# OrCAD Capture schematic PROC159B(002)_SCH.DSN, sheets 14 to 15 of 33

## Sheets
14 12. ETHERNET POWERS: size C; title: ETHERNET POWERS
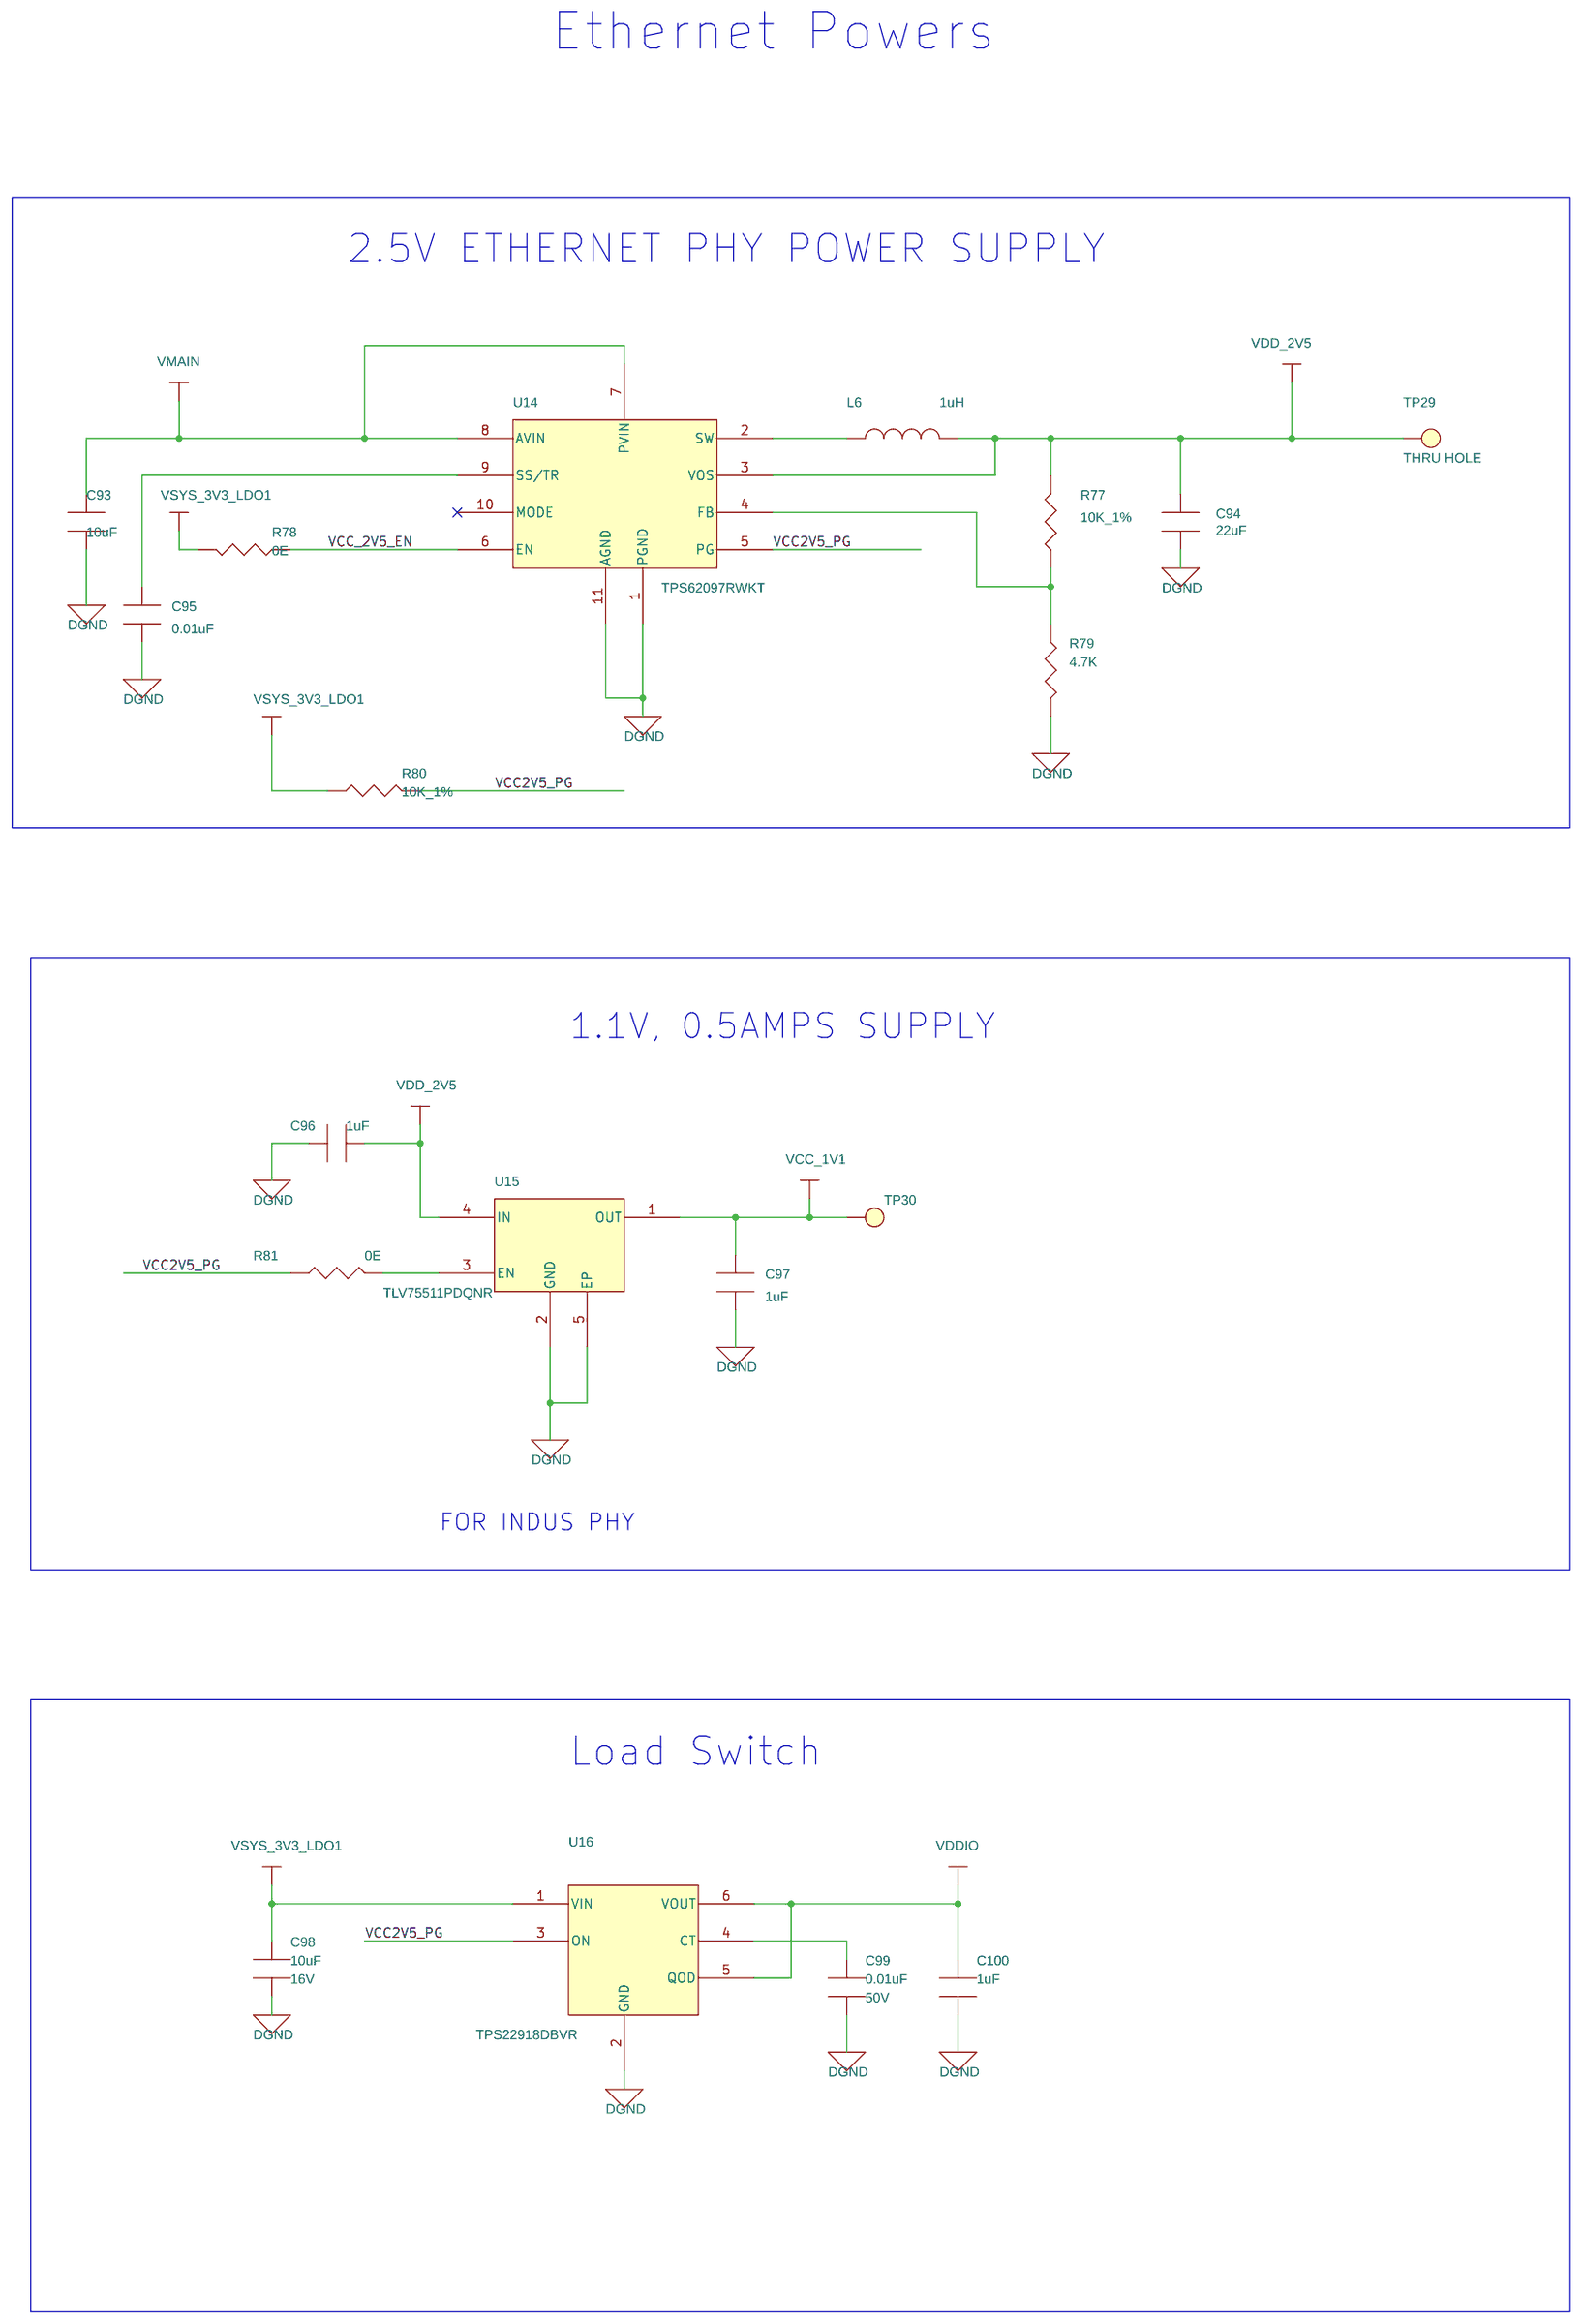
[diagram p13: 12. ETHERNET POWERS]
15 19. SOC-ICSS DP8386(Indust): size C; title: SOC-ICSS DP8386(Indus)
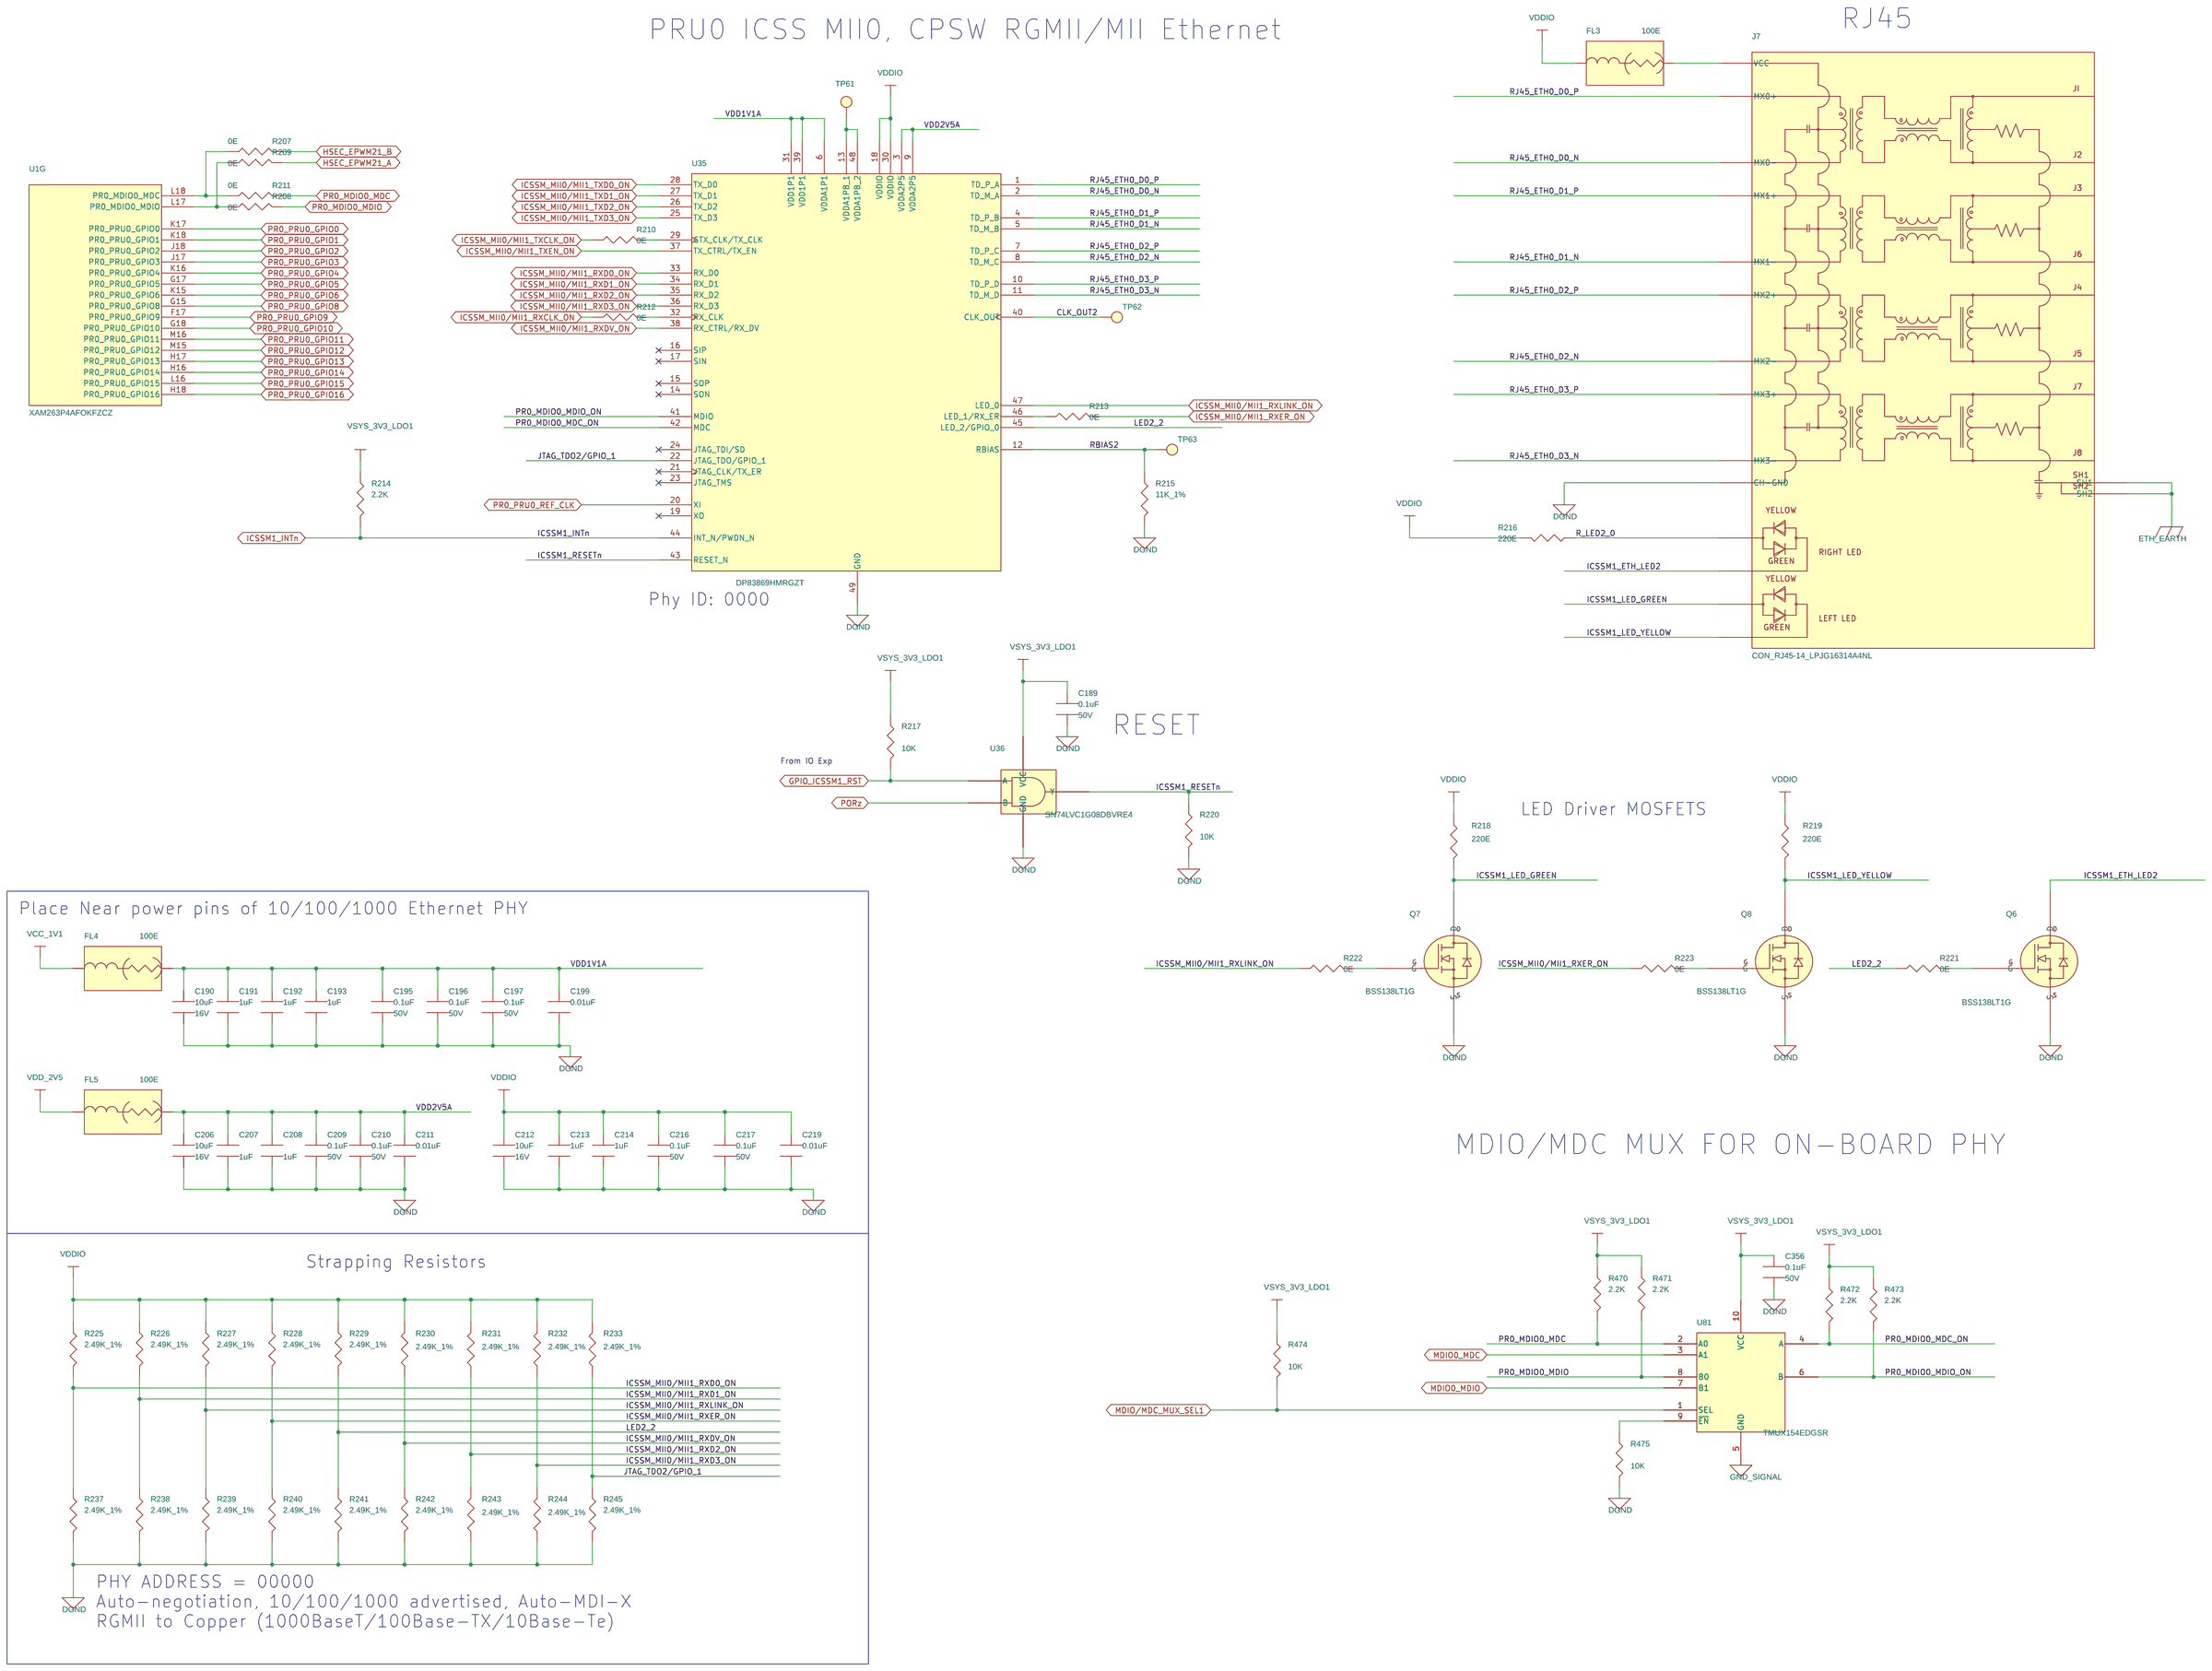
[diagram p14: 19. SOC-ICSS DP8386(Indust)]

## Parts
sheet 12. ETHERNET POWERS
C93  10uF  [CAP0603_1]
C94  22uF  [CAP0603_1]
C95  0.01uF  [CAP0402_0-75]
C96  1uF  [CAP0201_0-5]
C97  1uF  [CAP0201_0-5]
C98  10uF  [CAP0603_1]
C99  0.01uF  [CAP0402_0-75]
C100  1uF  [CAP0402_0-75]
L6  1uH  [IND_IHLP2020B_230X215_SMD]
R77  10K_1%  [RES0402_0-5]
R78  0E  [RES0402_0-5]
R79  4.7K  [RES0402_0-5]
R80  10K_1%  [RES0402_0-5]
R81  0E  [RES0201_0-5]
TP29  THRU HOLE  [TP_40X65]
TP30  TP20_SMD  [TP20_SMD]
U14  TPS62097RWKT  [VQFNHR11_TPS62097_80X80_1]
U15  TLV75511PDQNR  [X2SON4_TLV71318P_40X40_0-4]
U16  TPS22918DBVR  [SOT23-6]
sheet 19. SOC-ICSS DP8386(Indust)
C189  0.1uF  [CAP0402_0-75]
C190  10uF  [CAP0603_1]
C191  1uF  [CAP0402_0-75]
C192  1uF  [CAP0402_0-75]
C193  1uF  [CAP0402_0-75]
C195  0.1uF  [CAP0402_0-75]
C196  0.1uF  [CAP0402_0-75]
C197  0.1uF  [CAP0402_0-75]
C199  0.01uF  [CAP0402_0-75]
C206  10uF  [CAP0603_1]
C207  1uF  [CAP0402_0-75]
C208  1uF  [CAP0402_0-75]
C209  0.1uF  [CAP0402_0-75]
C210  0.1uF  [CAP0402_0-75]
C211  0.01uF  [CAP0402_0-75]
C212  10uF  [CAP0603_1]
C213  1uF  [CAP0402_0-75]
C214  1uF  [CAP0402_0-75]
C216  0.1uF  [CAP0402_0-75]
C217  0.1uF  [CAP0402_0-75]
C219  0.01uF  [CAP0402_0-75]
C356  0.1uF  [CAP0402_0-75]
FL3  100E  [EMIFIL_BLM18R_0603]
FL4  100E  [EMIFIL_BLM18R_0603]
FL5  100E  [EMIFIL_BLM18R_0603]
J7  CON_RJ45-14_LPJG16314A4NL  [CON_RJ45-14_LPJG16314A4NL_S_R_T_13-6]
Q6  BSS138LT1G  [SOT23-123_1-2]
Q7  BSS138LT1G  [SOT23-123_1-2]
Q8  BSS138LT1G  [SOT23-123_1-2]
R207  0E  [RES0402_0-5]
R208  0E  [RES0402_0-5]
R209  0E  [RES0402_0-5]
R210  0E  [RES0402_0-5]
R211  0E  [RES0402_0-5]
R212  0E  [RES0402_0-5]
R213  0E  [RES0402_0-5]
R214  2.2K  [RES0402_0-5]
R215  11K_1%  [RES0402_0-5]
R216  220E  [RES0402_0-5]
R217  10K  [RES0402_0-5]
R218  220E  [RES0402_0-5]
R219  220E  [RES0402_0-5]
R220  10K  [RES0402_0-5]
R221  0E  [RES0402_0-5]
R222  0E  [RES0402_0-5]
R223  0E  [RES0402_0-5]
R225  2.49K_1%  [RES0402_0-5]
R226  2.49K_1%  [RES0402_0-5]
R227  2.49K_1%  [RES0402_0-5]
R228  2.49K_1%  [RES0402_0-5]
R229  2.49K_1%  [RES0402_0-5]
R230  2.49K_1%  [RES0402_0-5]
R231  2.49K_1%  [RES0402_0-5]
R232  2.49K_1%  [RES0402_0-5]
R233  2.49K_1%  [RES0402_0-5]
R237  2.49K_1%  [RES0402_0-5]
R238  2.49K_1%  [RES0402_0-5]
R239  2.49K_1%  [RES0402_0-5]
R240  2.49K_1%  [RES0402_0-5]
R241  2.49K_1%  [RES0402_0-5]
R242  2.49K_1%  [RES0402_0-5]
R243  2.49K_1%  [RES0402_0-5]
R244  2.49K_1%  [RES0402_0-5]
R245  2.49K_1%  [RES0402_0-5]
R470  2.2K  [RES0402_0-5]
R471  2.2K  [RES0402_0-5]
R472  2.2K  [RES0402_0-5]
R473  2.2K  [RES0402_0-5]
R474  10K  [RES0402_0-5]
R475  10K  [RES0402_0-5]
TP61  TP40_SMD  [TP40_SMD]
TP62  TP40_SMD  [TP40_SMD]
TP63  TP40_SMD  [TP40_SMD]
U1  XAM263P4AFOKFZCZ  [BGA324_31-49_590X590_1-4]  (sections A,B,C,D,E,F,G,H,I,J,K,L,M)
U35  DP83869HMRGZT  [QFN48_19-68_280X280_1_EP4-2]
U36  SN74LVC1G08DBVRE4  [SOT23-5]
U81  TMUX154EDGSR  [MSOP10_19-68_120X120_1-1]

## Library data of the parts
C93 C98 C190 C206 C212 = CAP: CAP CERAMIC 10uF 16V 20% X6S 0603; Chkd/date: VASANTHA/170117; Crtd /date: VASANTHA/170117; Custom_Duty: 15%; Customs_HS_Code: 85322990; Distributor_name: DIGIKEY; Distributor_part_number: 490-7198-1-ND; Footprint Path: Y:\MIS_DATABASE\Library\ALTIUM_TOOL\PCB_FOOTPRINTS\Altium_Footprint_Lib.PcbLib; Height: 0.90MM; Library Path: Y:\MIS_DATABASE\Library\ALTIUM_TOOL\SCHEMATICS_PARTS\MS_DISCRETE_Library.schlib; Mfr_name: MURATA; Mfr_part_number: GRM188C81C106MA73D; Mistral Part No: 120017010004-R; Package: 0603; Part_type: CAPACITORS\CERAMIC; Project: TRMM_SMART-M_PS; RoHS: RoHS; Temperature: -55°C+105°C; Tolerance: 20%; Voltage: 16V; Wattage: NA; Weight: 6.3mg; Datasheet: Y:\MIS_DATABASE\DATASHEETS\CAPACITORS\MURATA-GXX-SER_NOV17.PDF
C94 = CAP: CAP CERAMIC 22uF 6.3V 20% X5R 0603; Chkd/date: JEBRAN/090915; Crtd /date: JEBRAN/090915; Custom_Duty: 15%; Customs_HS_Code: 85322990; Distributor_name: DIGIKEY; Distributor_part_number: 490-7611-2-ND; Footprint Path: Y:\MIS_DATABASE\Library\ALTIUM_TOOL\PCB_FOOTPRINTS\Altium_Footprint_Lib.PcbLib; Height: 1.00MM; Library Path: Y:\MIS_DATABASE\Library\ALTIUM_TOOL\SCHEMATICS_PARTS\MS_DISCRETE_Library.schlib; Mfr_name: MURATA; Mfr_part_number: GRM188R60J226MEA0; Mistral Part No: 120015090007-R; Package: 0603; Part_type: CAPACITORS\CERAMIC; Project: OCTBTS_3000; RoHS: RoHS; Temperature: -55°C+85°C; Tolerance: 20%; Voltage: 6.3V; Wattage: NA; Weight: 6.3mg; Datasheet: Y:\MIS_DATABASE\DATASHEETS\CAPACITORS\MURATA-GXX-SER_NOV17.PDF
C95 C199 C211 C219 = CAP: CAP CERAMIC 0.01uF 50V 10% X7R 0402; Chkd/date: MANIRAJA/280319; Crtd /date: MANIRAJA/280319; Custom_Duty: 15%; Customs_HS_Code: 85322990; Distributor_name: DIGIKEY; Distributor_part_number: 490-4516-1-ND; Footprint Path: Y:\MIS_DATABASE\Library\ALTIUM_TOOL\PCB_FOOTPRINTS\Altium_Footprint_Lib.PcbLib; Height: 0.55MM; Library Path: Y:\MIS_DATABASE\Library\ALTIUM_TOOL\SCHEMATICS_PARTS\MS_DISCRETE_Library.schlib; Mfr_name: MURATA; Mfr_part_number: GRM155R71H103KA88D; Mistral Part No: 120009030025-R; Package: 0402; Part_type: CAPACITORS\CERAMIC; Project: G4_SVGA; RoHS: RoHS; Temperature: -55°C+125°C; Tolerance: 10%; Voltage: 50V; Wattage: NA; Weight: 0.65mg; Datasheet: Y:\MIS_DATABASE\DATASHEETS\CAPACITORS\GRM155R71H103KA88D.PDF
C96 C97 = CAP: CAP CERAMIC 1uF 16V 20% X5R 0201; Chkd/date: MANIRAJA/300520; Crtd /date: ALVY/260520; Custom_Duty: 15%; Customs_HS_Code: 85322990; Distributor_name: DIGIKEY; Distributor_part_number: 490-18654-1-ND; Footprint Path: Y:\MIS_DATABASE\Library\ALTIUM_TOOL\PCB_FOOTPRINTS\Altium_Footprint_Lib.PcbLib; Height: 0.39MM; Library Path: Y:\MIS_DATABASE\Library\ALTIUM_TOOL\SCHEMATICS_PARTS\MS_DISCRETE_Library.schlib; Mfr_name: MURATA; Mfr_part_number: GRM033R61C105ME15D; Mistral Part No: 120018090038-R; Package: 0201; Part_type: CAPACITORS\CERAMIC; Project: QCS610_NANOSOM; RoHS: RoHS; Temperature: -55°C+85°C; Tolerance: 20%; Voltage: 16V; Wattage: NA; Weight: 0.33mg; Datasheet: Y:\MIS_DATABASE\DATASHEETS\CAPACITORS\GRM033R61C105ME15.PDF
C99 = CAP: CAP CERAMIC 0.01uF 50V 10% X7R 0402; Assembly_Instruction: DNI; Chkd/date: MANIRAJA/280319; Crtd /date: MANIRAJA/280319; Custom_Duty: 15%; Customs_HS_Code: 85322990; Distributor_name: DIGIKEY; Distributor_part_number: 490-4516-1-ND; Footprint Path: Y:\MIS_DATABASE\Library\ALTIUM_TOOL\PCB_FOOTPRINTS\Altium_Footprint_Lib.PcbLib; Height: 0.55MM; Library Path: Y:\MIS_DATABASE\Library\ALTIUM_TOOL\SCHEMATICS_PARTS\MS_DISCRETE_Library.schlib; Mfr_name: MURATA; Mfr_part_number: GRM155R71H103KA88D; Mistral Part No: 120009030025-R; Package: 0402; Part_type: CAPACITORS\CERAMIC; Project: G4_SVGA; RoHS: RoHS; Temperature: -55°C+125°C; Tolerance: 10%; Voltage: 50V; Wattage: NA; Weight: 0.65mg; Datasheet: Y:\MIS_DATABASE\DATASHEETS\CAPACITORS\GRM155R71H103KA88D.PDF
C100 C191-C193 C207 C208 C213 C214 = CAP: CAP CERAMIC 1uF 25V 10% X6S 0402; Chkd/date: MANIRAJA/140518; Crtd /date: ALVY/140518; Custom_Duty: 15%; Customs_HS_Code: 85322990; Distributor_name: DIGIKEY; Distributor_part_number: 490-10014-1-ND; Footprint Path: Y:\MIS_DATABASE\Library\ALTIUM_TOOL\PCB_FOOTPRINTS\Altium_Footprint_Lib.PcbLib; Height: 0.60MM; Library Path: Y:\MIS_DATABASE\Library\ALTIUM_TOOL\SCHEMATICS_PARTS\MS_DISCRETE_Library.schlib; Mfr_name: MURATA; Mfr_part_number: GRM155C81E105KE11D; Mistral Part No: 120018050004-R; Package: 0402; Part_type: CAPACITORS\CERAMIC; Project: TI_SVB_MAXWELL_DUT; RoHS: RoHS; Temperature: -55°C+105°C; Tolerance: 10%; Voltage: 25V; Wattage: NA; Weight: 6mg; Datasheet: Y:\MIS_DATABASE\DATASHEETS\CAPACITORS\GRM155C81E105KE11X.PDF
L6 = INDUCTOR: IND POWER 1uH 7A 20% SMD; Chkd/date: BAVISH/260911; Crtd /date: CHAITHANYA/260911; Custom_Duty: 24%; Customs_HS_Code: 85437099; Distributor_name: DIGIKEY; Distributor_part_number: 541-1087-1-ND; Height: 2.00MM; Mfr_name: VISHAY; Mfr_part_number: IHLP2020BZER1R0M01; Mistral Part No: 130011090053-R; Package: SMD; Project: GEMYC; RoHS: RoHS; Temperature: -55°C+125°C; Tolerance: 20%; Voltage: NA; Wattage: NA; Weight: NA; Datasheet: Y:\MIS_DATABASE\DATASHEETS\DISCRETES\INDUCTORS\IHLP2020BZ-01.PDF
R77 R80 = RESISTOR: RES 10K 1/16W 1% 0402; Chkd/date: VASANTHA/201216; Crtd /date: GEETHA/290506; Custom_Duty: 15%; Customs_HS_Code: 85332119; Distributor_name: DIGIKEY; Distributor_part_number: 311-10.0KLRTR-ND; Footprint Path: Y:\MIS_DATABASE\Library\ALTIUM_TOOL\PCB_FOOTPRINTS\Altium_Footprint_Lib.PcbLib; Height: 0.40MM; Library Path: Y:\MIS_DATABASE\Library\ALTIUM_TOOL\SCHEMATICS_PARTS\MS_DISCRETE_Library.schlib; Mfr_name: YAGEO AMERICA; Mfr_part_number: RC0402FR-0710KL; Mistral Part No: 110015090015-R; Package: 0402; Part_type: RESISTORS\FIXED; Project: VOCERA; RoHS: RoHS; Temperature: -55°C+155°C; Tolerance: 1%; Voltage: NA; Wattage: 1/16W; Weight: 0.65mg; Datasheet: Y:\MIS_DATABASE\DATASHEETS\RESISTORS\RCXXXXL-SER_MAR18.PDF
R78 R207-R213 R221-R223 = RESISTOR: RES 0E 1/10W JUMPER 0402; Chkd/date: VASANTHA/061216; Crtd /date: NAVEED/201014; Custom_Duty: 15%; Customs_HS_Code: 85332119; Distributor_name: DIGIKEY; Distributor_part_number: P0.0JCT-ND; Footprint Path: Y:\MIS_DATABASE\Library\ALTIUM_TOOL\PCB_FOOTPRINTS\Altium_Footprint_Lib.PcbLib; Height: 0.40MM; IBISSP_MODLES: VALUE REPEATING 2 TIME; Library Path: Y:\MIS_DATABASE\Library\ALTIUM_TOOL\SCHEMATICS_PARTS\MS_DISCRETE_Library.schlib; Mfr_name: PANASONIC-ECG; Mfr_part_number: ERJ-2GE0R00X; Mistral Part No: 110018030052-R; Package: 0402; Part_type: RESISTORS\FIXED; Project: AEGIS POM; RoHS: RoHS; Temperature: -55°C+155°C; Tolerance: NA; Voltage: NA; Wattage: 1/10W; Weight: 0.8mg; Datasheet: Y:\MIS_DATABASE\DATASHEETS\RESISTORS\PAN-ERJSER_NOV17.PDF
R79 = RESISTOR: RES 4.7K 1/16W 5% 0402; Chkd/date: VASANTHA/281216; Crtd /date: BAVISH/010611; Custom_Duty: 15%; Customs_HS_Code: 85332119; Distributor_name: DIGIKEY; Distributor_part_number: 541-4.7KJCT-ND; Footprint Path: Y:\MIS_DATABASE\Library\ALTIUM_TOOL\PCB_FOOTPRINTS\Altium_Footprint_Lib.PcbLib; Height: 0.40MM; Library Path: Y:\MIS_DATABASE\Library\ALTIUM_TOOL\SCHEMATICS_PARTS\MS_DISCRETE_Library.schlib; Mfr_name: VISHAY; Mfr_part_number: CRCW04024K70JNED; Mistral Part No: 110011060001-R; Package: 0402; Part_type: RESISTORS\FIXED; Project: AM4515_EVM_LCD; RoHS: RoHS; Temperature: -55°C+155°C; Tolerance: 5%; Voltage: NA; Wattage: 1/16W; Weight: 0.65mg; Datasheet: Y:\MIS_DATABASE\DATASHEETS\RESISTORS\CRCW0603.PDF
R81 = RESISTOR: RES 0E 1/20W 5% 0201; Chkd/date: NAVEED/301214; Crtd /date: MUDDU/120710; Custom_Duty: 15%; Customs_HS_Code: 85332119; Distributor_name: DIGIKEY; Distributor_part_number: 311-0.0NCT-ND; Footprint Path: Y:\MIS_DATABASE\Library\ALTIUM_TOOL\PCB_FOOTPRINTS\Altium_Footprint_Lib.PcbLib; Height: 0.26MM; Library Path: Y:\MIS_DATABASE\Library\ALTIUM_TOOL\SCHEMATICS_PARTS\MS_DISCRETE_Library.schlib; Mfr_name: YAGEO AMERICA; Mfr_part_number: RC0201JR-070RL; Mistral Part No: 110010070067-R; Package: 0201; Part_type: RESISTORS\FIXED; Project: PB_BUGBASE; RoHS: RoHS; Temperature: -55°C+125°C; Tolerance: 5%; Voltage: NA; Wattage: 1/20W; Weight: 0.17mg; Datasheet: Y:\MIS_DATABASE\DATASHEETS\RESISTORS\RCXXXXL-SER_MAR18.PDF
TP29 = TESTPOINT: TESTPOINT 1.0MM DRILL PTH; Chkd/date: MAZHAR/271211; Crtd /date: SHREESHAIL/041005; Distributor_name: NA; Distributor_part_number: NA; Height: NA; Mfr_name: LOCAL; Mistral Part No: 130009030938; Package: THRU-HOLE; Project: HSE; Datasheet: NA
TP30 = TESTPOINT: TESTPOINT CIR 20 SMD; Chkd/date: SHREESHAIL/171006; Crtd /date: MAZHAR/171006; Custom_Duty: NA; Customs_HS_Code: NA; Distributor_name: NA; Distributor_part_number: NA; Footprint Path: Y:\MIS_DATABASE\Library\ALTIUM_TOOL\PCB_FOOTPRINTS\Altium_Footprint_Lib.PcbLib; Height: NA; Library Path: Y:\MIS_DATABASE\Library\ALTIUM_TOOL\SCHEMATICS_PARTS\MS_DISCRETE_Library.schlib; MECHANICAL 3D STEP FILE: NA; Mfr_name: LOCAL; Mistral Part No: NA; Package: SMD; Project: BT MODULE_CSRBC04; RoHS: NA; Temperature: NA; Tolerance: NA; Voltage: NA; Wattage: NA; Weight: NA; Datasheet: NA
U14 = TPS62097RWKT_VQFNHR11: IC 2A SYNCHRONOUS STEP DOWN CONVERTER WITH IDCS CONTROL VQFN-HR11; Chkd/date: MANIRAJA/270917; Crtd /date: MANIRAJA/270917; Custom_Duty: 15%; Customs_HS_Code: 85423100; Distributor_name: DIGIKEY; Distributor_part_number: 296-43330-1-ND; Height: 1.00MM; Mfr_name: TEXAS INSTRUMENTS; Mistral Part No: 142017090025-R; Package: VQFN-HR11; Part_type: ICS\POWER\CONVERTER; Project: TI_MAXIE_CPB; RoHS: RoHS; Temperature: -40°C+125°C; Tolerance: NA; Voltage: NA; Wattage: NA; Weight: NA; Datasheet: Y:\MIS_DATABASE\DATASHEETS\ICS\POWER\TPS62097.PDF
U15 = TLV71318PDQNR_X2SON4: IC 500mA 1.1V LOW IQ LDO REGULATOR X2SON-4; Chkd/date: MANIRAJA/011021; Crtd /date: ALVY/011021; Custom_Duty: 15%; Customs_HS_Code: 85423100; Distributor_name: DIGIKEY; Distributor_part_number: 296-51784-1-ND; Footprint Path: Y:\MIS_DATABASE\Library\ALTIUM_TOOL\PCB_FOOTPRINTS\Altium_Footprint_Lib.PcbLib; Height: 0.40MM; Library Path: Y:\MIS_DATABASE\Library\ALTIUM_TOOL\SCHEMATICS_PARTS\MS_MISCPOWER_Library.schlib; Mfr_name: TEXAS INSTRUMENTS; Mistral Part No: 142021100002-R; Package: X2SON-4; Part_type: ICS\POWER\VOLTAGE REGULATOR; Project: TI_AM62x SKEVM_BRD; RoHS: RoHS; Temperature: -40°C+125°C; Tolerance: NA; Voltage: NA; Wattage: NA; Weight: 1.1mg; Datasheet: Y:\MIS_DATABASE\DATASHEETS\ICS\POWER\TLV755P.PDF
U16 = TPS22918DBVR_SOT23-6: IC ON RESISTANCE LOAD SWITCH SOT23-6; Chkd/date: VASANTHA/130516; Crtd /date: VASANTHA/130516; Custom_Duty: 15%; Customs_HS_Code: 85423100; Distributor_name: DIGIKEY; Distributor_part_number: TPS22918DBVR-ND; Height: 1.45MM; Mfr_name: TEXAS INSTRUMENTS; Mistral Part No: 142016050007-R; Part_type: ICS\POWER; Project: TMDXCSK8127; RoHS: RoHS; Temperature: -40°C to 105°C; Tolerance: NA; Voltage: NA; Wattage: NA; Weight: NA; Datasheet: Y:\MIS_DATABASE\DATASHEETS\ICS\POWER\TPS22918DBV.PDF
C189 C356 = CAP: CAP CERAMIC 0.1uF 50V 10% X7R 0402; Automotive Alternate_mfr_name: TDK; Automotive Alternate_mfr_part_number: CGA2B3X7R1H104K050BB; Chkd/date: MANIRAJA/261020; Crtd /date: ALVY/211020; Custom_Duty: 15%; Customs_HS_Code: 85322990; Direct Alternate_mfr_name: TDK; Direct Alternate_mfr_part_number: C1005X7R1H104K050BE; Distributor_name: DIGIKEY; Distributor_part_number: 490-10700-1-ND; Footprint Path: Y:\MIS_DATABASE\Library\ALTIUM_TOOL\PCB_FOOTPRINTS\Altium_Footprint_Lib.PcbLib; Height: 0.55MM; Library Path: Y:\MIS_DATABASE\Library\ALTIUM_TOOL\SCHEMATICS_PARTS\MS_DISCRETE_Library.schlib; Mfr_name: MURATA; Mfr_part_number: GRM155R71H104KE14D; Mistral Part No: 120011100014-R; Package: 0402; Part_type: CAPACITORS\CERAMIC; Project: J7_CP; RoHS: RoHS; Temperature: -55°C+125°C; Tolerance: 10%; Voltage: 50V; Wattage: NA; Weight: 3.1mg; Datasheet: Y:\MIS_DATABASE\DATASHEETS\CAPACITORS\GRM155R71H104KE14.PDF
C195-C197 C209 C210 C216 C217 = CAP: CAP CERAMIC 0.1uF 50V 10% X7R 0402; Chkd/date: MANIRAJA/261020; Crtd /date: ALVY/211020; Custom_Duty: 15%; Customs_HS_Code: 85322990; Distributor_name: DIGIKEY; Distributor_part_number: 490-10700-1-ND; Footprint Path: Y:\MIS_DATABASE\Library\ALTIUM_TOOL\PCB_FOOTPRINTS\Altium_Footprint_Lib.PcbLib; Height: 0.55MM; Library Path: Y:\MIS_DATABASE\Library\ALTIUM_TOOL\SCHEMATICS_PARTS\MS_DISCRETE_Library.schlib; Mfr_name: MURATA; Mfr_part_number: GRM155R71H104KE14D; Mistral Part No: 120011100014-R; Package: 0402; Part_type: CAPACITORS\CERAMIC; Project: J7_CP; RoHS: RoHS; Temperature: -55°C+125°C; Tolerance: 10%; Voltage: 50V; Wattage: NA; Weight: 3.1mg; Datasheet: Y:\MIS_DATABASE\DATASHEETS\CAPACITORS\GRM155R71H104KE14.PDF
FL3-FL5 = EMIFILTER_IND: PASSIVE FILTER EMI 100E 2A 0603; Chkd/date: BAVISH/170811; Crtd /date: CHAITHANYA/170811; Custom_Duty: 24%; Customs_HS_Code: 85437099; Distributor_name: DIGIKEY; Distributor_part_number: BLM18EG101TN1D-ND; Footprint Path: Y:\MIS_DATABASE\Library\ALTIUM_TOOL\PCB_FOOTPRINTS\Altium_Footprint_Lib.PcbLib; Height: 0.65MM; Library Path: Y:\MIS_DATABASE\Library\ALTIUM_TOOL\SCHEMATICS_PARTS\MS_FILTER_Library.schlib; Mfr_name: MURATA; Mfr_part_number: BLM18EG101TN1D; Mistral Part No: 130011080028-R; Package: 0603; Part_type: FILTER; Project: CPCI3GADC_CARD; RoHS: RoHS; Temperature: -55°C+125°C; Tolerance: NA; Voltage: NA; Wattage: NA; Weight: NA; Datasheet: Y:\MIS_DATABASE\DATASHEETS\DISCRETES\INDUCTORS\BLM18E.PDF
J7 = CON_RJ45-14_LPJG16314A4NL: CON RJ-45 FEMALE 14POS RT TH; Chkd/date: VASANTHA/150714; Crtd /date: BALACHANDAR/120614; Custom_Duty: 24%; Customs_HS_Code: 85369090; Distributor_name: NA; Distributor_part_number: NA; Footprint Path: Y:\MIS_DATABASE\Library\ALTIUM_TOOL\PCB_FOOTPRINTS\Altium_Footprint_Lib.PcbLib; Height: 13.60MM; Library Path: Y:\MIS_DATABASE\Library\ALTIUM_TOOL\SCHEMATICS_PARTS\MS_CONNECTOR_Library.schlib; Mfr_name: LINK-PP; Mfr_part_number: LPJG16314A4NL; Mistral Part No: 150014060029-R; Package: THRU-HOLE; Part_type: CONNECTOR\JACK; Project: AEGIS; RoHS: RoHS; Temperature: -0°C+70°C; Tolerance: NA; Voltage: NA; Wattage: NA; Weight: NA; Datasheet: Y:\MIS_DATABASE\DATASHEETS\CONNECTORS\LPJG16314A4NL.PDF
Q6-Q8 = MOSFET_BSS138W: IC MOSFET N-CHANNEL 50V 200mA SOT23-3; Chkd/date: MANIRAJA/250219; Crtd /date: JEBRAN/060416; Custom_Duty: 15%; Customs_HS_Code: 85423100; Distributor_name: DIGIKEY; Distributor_part_number: BSS138LT1GOSCT-ND; Footprint Path: Y:\MIS_DATABASE\Library\ALTIUM_TOOL\PCB_FOOTPRINTS\Altium_Footprint_Lib.PcbLib; Height: 1.11MM; Library Path: Y:\MIS_DATABASE\Library\ALTIUM_TOOL\SCHEMATICS_PARTS\MS_MOSFET_Library.schlib; Mfr_name: ON SEMICONDUCTOR; Mistral Part No: 142016040001-R; Package: SOT23-3; Part_type: ICS\POWER\MOSFET; Project: LRDE_ABCM; RoHS: RoHS; Temperature: -55°C+150°C; Tolerance: NA; Voltage: NA; Wattage: NA; Weight: 8mg; Datasheet: Y:\MIS_DATABASE\DATASHEETS\DISCRETES\TRANSISTORS_FETS\BSS138LT1G.PDF
R214 R470-R473 = RESISTOR: RES 2.2K 1/10W 5% 0402; Chkd/date: SHREESHAIL/210406; Crtd /date: GEETHA/200406; Custom_Duty: 15%; Customs_HS_Code: 85332119; Distributor_name: DIGIKEY; Distributor_part_number: P2.2KJCT-ND; Footprint Path: Y:\MIS_DATABASE\Library\ALTIUM_TOOL\PCB_FOOTPRINTS\Altium_Footprint_Lib.PcbLib; Height: 0.40MM; Library Path: Y:\MIS_DATABASE\Library\ALTIUM_TOOL\SCHEMATICS_PARTS\MS_DISCRETE_Library.schlib; Mfr_name: PANASONIC-ECG; Mfr_part_number: ERJ-2GEJ222X; Mistral Part No: 110009030429-R; Package: 0402; Part_type: RESISTORS\FIXED; Project: RED EYE; RoHS: RoHS; Temperature: -55°C+155°C; Tolerance: 5%; Voltage: NA; Wattage: 1/10W; Weight: 0.8mg; Datasheet: Y:\MIS_DATABASE\DATASHEETS\RESISTORS\PAN-ERJSER_NOV17.PDF
R215 = RESISTOR: RES 11K 1/16W 1% 0402; Chkd/date: VASANTHA/251115; Crtd /date: VASANTHA/251115; Custom_Duty: 15%; Customs_HS_Code: 85332119; Distributor_name: DIGIKEY; Distributor_part_number: 311-11.0KLRCT-ND; Footprint Path: Y:\MIS_DATABASE\Library\ALTIUM_TOOL\PCB_FOOTPRINTS\Altium_Footprint_Lib.PcbLib; Height: 0.40MM; Library Path: Y:\MIS_DATABASE\Library\ALTIUM_TOOL\SCHEMATICS_PARTS\MS_DISCRETE_Library.schlib; Mfr_name: YAGEO AMERICA; Mfr_part_number: RC0402FR-0711KL; Mistral Part No: 110015110012-R; Package: 0402; Part_type: RESISTORS\FIXED; Project: TI_VLAN_SWITCH; RoHS: RoHS; Temperature: -55°C+155°C; Tolerance: 1%; Voltage: NA; Wattage: 1/16W; Weight: 0.65mg; Datasheet: Y:\MIS_DATABASE\DATASHEETS\RESISTORS\RCXXXXL-SER_MAR18.PDF
R216 R218 R219 = RESISTOR: RES 220E 1/10W 5% 0402; Chkd/date: VASANTHA/291216; Crtd /date: GEETHA/260406; Custom_Duty: 15%; Customs_HS_Code: 85332119; Distributor_name: DIGIKEY; Distributor_part_number: P220JCT-ND; Footprint Path: Y:\MIS_DATABASE\Library\ALTIUM_TOOL\PCB_FOOTPRINTS\Altium_Footprint_Lib.PcbLib; Height: 0.40MM; Library Path: Y:\MIS_DATABASE\Library\ALTIUM_TOOL\SCHEMATICS_PARTS\MS_DISCRETE_Library.schlib; Mfr_name: PANASONIC-ECG; Mfr_part_number: ERJ-2GEJ221X; Mistral Part No: 110009030506-R; Package: 0402; Part_type: RESISTORS\FIXED; Project: RED EYE; RoHS: RoHS; Temperature: -55°C+155°C; Tolerance: 5%; Voltage: NA; Wattage: 1/10W; Weight: 0.8mg; Datasheet: Y:\MIS_DATABASE\DATASHEETS\RESISTORS\PAN-ERJSER_NOV17.PDF
R217 R220 R474 R475 = RESISTOR: RES 10K 1/16W 5% 0402; Chkd/date: VASANTHA/061216; Crtd /date: MAZHAR/230805; Custom_Duty: 15%; Customs_HS_Code: 85332119; Distributor_name: DIGIKEY; Distributor_part_number: 311-10KJRCT-ND; Footprint Path: Y:\MIS_DATABASE\Library\ALTIUM_TOOL\PCB_FOOTPRINTS\Altium_Footprint_Lib.PcbLib; Height: 0.40MM; Library Path: Y:\MIS_DATABASE\Library\ALTIUM_TOOL\SCHEMATICS_PARTS\MS_DISCRETE_Library.schlib; Mfr_name: YAGEO AMERICA; Mfr_part_number: RC0402JR-0710KL; Mistral Part No: 110011060021-R; Package: 0402; Part_type: RESISTORS\FIXED; Project: HSE; RoHS: RoHS; Temperature: -55°C+155°C; Tolerance: 5%; Voltage: NA; Wattage: 1/16W; Weight: 0.65mg; Datasheet: Y:\MIS_DATABASE\DATASHEETS\RESISTORS\RCXXXXL-SER_MAR18.PDF
R225-R230 R233 R243 R244 = RESISTOR: RES 2.49K 1/10W 1% 0402; Assembly_Instruction: DNI; Chkd/date: MANIRAJA/270718; Crtd /date: ALVY/270718; Custom_Duty: 15%; Customs_HS_Code: 85332119; Distributor_name: DIGIKEY; Distributor_part_number: P2.49KLCT-ND; Footprint Path: Y:\MIS_DATABASE\Library\ALTIUM_TOOL\PCB_FOOTPRINTS\Altium_Footprint_Lib.PcbLib; Height: 0.40MM; Library Path: Y:\MIS_DATABASE\Library\ALTIUM_TOOL\SCHEMATICS_PARTS\MS_DISCRETE_Library.schlib; Mfr_name: PANASONIC-ECG; Mfr_part_number: ERJ-2RKF2491X; Mistral Part No: 110018070020-R; Package: 0402; Part_type: RESISTORS\FIXED; Project: TI_J7SVB_ETHERNET_AOC; RoHS: RoHS; Temperature: -55°C+155°C; Tolerance: 1%; Voltage: NA; Wattage: 1/10W; Weight: 0.8mg; Datasheet: Y:\MIS_DATABASE\DATASHEETS\RESISTORS\PAN-ERJSER_NOV17.PDF
R231 R232 R237-R242 R245 = RESISTOR: RES 2.49K 1/10W 1% 0402; Chkd/date: MANIRAJA/270718; Crtd /date: ALVY/270718; Custom_Duty: 15%; Customs_HS_Code: 85332119; Distributor_name: DIGIKEY; Distributor_part_number: P2.49KLCT-ND; Footprint Path: Y:\MIS_DATABASE\Library\ALTIUM_TOOL\PCB_FOOTPRINTS\Altium_Footprint_Lib.PcbLib; Height: 0.40MM; Library Path: Y:\MIS_DATABASE\Library\ALTIUM_TOOL\SCHEMATICS_PARTS\MS_DISCRETE_Library.schlib; Mfr_name: PANASONIC-ECG; Mfr_part_number: ERJ-2RKF2491X; Mistral Part No: 110018070020-R; Package: 0402; Part_type: RESISTORS\FIXED; Project: TI_J7SVB_ETHERNET_AOC; RoHS: RoHS; Temperature: -55°C+155°C; Tolerance: 1%; Voltage: NA; Wattage: 1/10W; Weight: 0.8mg; Datasheet: Y:\MIS_DATABASE\DATASHEETS\RESISTORS\PAN-ERJSER_NOV17.PDF
TP61-TP63 = TESTPOINT: TESTPOINT CIR 40 SMD; Chkd/date: MAZHAR/190505; Crtd /date: MAZHAR/190505; Distributor_name: NA; Distributor_part_number: NA; Footprint Path: Y:\MIS_DATABASE\Library\ALTIUM_TOOL\PCB_FOOTPRINTS\Altium_Footprint_Lib.PcbLib; Height: NA; Library Path: Y:\MIS_DATABASE\Library\ALTIUM_TOOL\SCHEMATICS_PARTS\MS_DISCRETE_Library.schlib; MECHANICAL 3D STEP FILE: NA; Mfr_name: LOCAL; Mistral Part No: 130009030933; Package: SMD; Project: RAINIER-3; RoHS: NA; Temperature: NA; Tolerance: NA; Voltage: NA; Wattage: NA; Weight: NA; Datasheet: NA
U1 = XAM263P4ASOKFZCZ_BGA324: IC SIP AM263P SoC BGA324; Chkd/date: PRADEEP/030124; Crtd /date: PRADEEP/030124; Custom_Duty: 15%; Customs_HS_Code: 85423100; Distributor_name: NA; Distributor_part_number: NA; Footprint Path: Y:\MIS_DATABASE\Library\ALTIUM_TOOL\PCB_FOOTPRINTS\Altium_Footprint_Lib.PcbLib; Height: 1.40MM; MECHANICAL 3D STEP FILE: NA; Mfr_name: TEXAS INSTRUMENTS; Mistral Part No: 141324010001; Package: BGA324; Part_type: ICS\DIGITAL\FPGA; Project: AM263P_CC; RoHS: RoHS; Temperature: NA; Tolerance: NA; Voltage: NA; Wattage: NA; Weight: NA; Datasheet: Y:\MIS_DATABASE\DATASHEETS\ICS\INTERFACE\ZCZ0324A.PDF
U35 = DP83869HM_VQFN48: IC ETHERNET TRANSCEIVER 10/100/1000 WITH COPPER AND FIBRE INTERFACE VQFN48; Chkd/date: MANIRAJA/060519; Crtd /date: ALVY/060519; Custom_Duty: 15%; Customs_HS_Code: 85423100; Distributor_name: DIGIKEY; Distributor_part_number: 296-53377-1-ND; Footprint Path: Y:\MIS_DATABASE\Library\ALTIUM_TOOL\PCB_FOOTPRINTS\Altium_Footprint_Lib.PcbLib; Height: 1.00MM; Library Path: Y:\MIS_DATABASE\Library\ALTIUM_TOOL\SCHEMATICS_PARTS\MS_TELECOM_Library.schlib; Mfr_name: TEXAS INSTRUMENTS; Mistral Part No: 143019050002-R; Package: VQFN48; Part_type: ICS\TELECOM\TRANSCEIVER; Project: J7ES_ENET_DP83869HM_EXP; RoHS: RoHS; Temperature: -40°C+125°C; Tolerance: NA; Voltage: NA; Wattage: NA; Weight: NA; Datasheet: Y:\MIS_DATABASE\DATASHEETS\ICS\TELECOM\DP83869HM.PDF
U36 = SN74LVC1G08DBVRE4_SOT23-5: IC SINGLE 2-INPUT POSITIVE AND GATE SOT23-5; Automotive Alternate_mfr_name: TEXAS INSTRUMENTS; Automotive Alternate_mfr_part_number: SN74LVC1G08QDBVRQ1; Chkd/date: SUHAS/221010; Crtd /date: USMAN/151008; Custom_Duty: 15%; Customs_HS_Code: 85423100; Distributor_name: DIGIKEY; Distributor_part_number: SN74LVC1G08DBVRE4-ND; Height: 1.45MM; Mfr_name: TEXAS INSTRUMENTS; Mistral Part No: 141009060026-R; Part_type: ICS\DIGITAL\GATES; Project: KHAN_MAIN; RoHS: Sb/ Br FREE; Temperature: -40°C+85°C; Datasheet: Y:\MIS_DATABASE\DATASHEETS\ICS\DIGITAL\GATES\SN74LVC1G08.PDF
U81 = TMUX154EDGSR_VSSOP10: IC ESD PROTECTED 2-CH 2:1 SWITCH WITH POWERED-OFF PROTECTION VSSOP10; Chkd/date: MANIRAJA/040918; Crtd /date: MANIRAJA/040918; Custom_Duty: 15%; Customs_HS_Code: 85423100; Distributor_name: DIGIKEY; Distributor_part_number: 296-48347-1-ND; Footprint Path: Y:\MIS_DATABASE\Library\ALTIUM_TOOL\PCB_FOOTPRINTS\Altium_Footprint_Lib.PcbLib; Height: 1.10MM; Library Path: Y:\MIS_DATABASE\Library\ALTIUM_TOOL\SCHEMATICS_PARTS\MS_ANALOG-APPLICATION_Library.schlib; Mfr_name: TEXAS INSTRUMENTS; Mistral Part No: 140118090001-R; Package: VSSOP10; Part_type: ICS\ANALOG\SWITCH; Project: DLRL_DFP_ATRUC CARD; RoHS: RoHS; Temperature: -40°C+85°C; Tolerance: NA; Voltage: NA; Wattage: NA; Weight: NA; Datasheet: Y:\MIS_DATABASE\DATASHEETS\ICS\ANALOG\TMUX154EXXX.PDF

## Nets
DGND: C93.2 C94.2 C95.2 C96.2 C97.2 C98.2 C99.2 C100.2 C189.2 C190.2 C191.2 C192.2 C193.2 C195.2 C196.2 C197.2 C199.2 C206.2 C207.2 C208.2 C209.2 C210.2 C211.2 C212.2 C213.2 C214.2 C216.2 C217.2 C219.2 C356.2 J7.1(CH-GND) Q6.2(S) Q7.2(S) Q8.2(S) R79.2 R215.2 R220.1 R237.2 R238.2 R239.2 R240.2 R241.2 R242.2 R243.1 R244.1 R245.2 R475.1 U14.1(PGND) U14.11(AGND) U15.2(GND) U15.5(EP) U16.2(GND) U35.49(GND) U36.3(GND) U81.5(GND) ; also on sheet 1 2 3 4 6 7 8 9 10 11 12 13 16 17 24 25 26 27 28 29 30 32 33
VCC2V5_PG: R80.2 R81.1 U14.5(PG) U16.3(ON)
VCC_1V1: C97.1 FL4.1 TP30.1(TP) U15.1(OUT)
VCC_2V5_EN: R78.1 U14.6(EN)
VDD1V1A: C190.1 C191.1 C192.1 C193.1 C195.1 C196.1 C197.1 C199.1 FL4.2 U35.6(VDDA1P1) U35.31(VDD1P1) U35.39(VDD1P1)
VDD2V5A: C206.1 C207.1 C208.1 C209.1 C210.1 C211.1 FL5.2 U35.3(VDDA2P5) U35.9(VDDA2P5)
VDD_2V5: C94.1 C96.1 FL5.1 L6.2 R77.2 TP29.1(TP) U14.3(VOS) U15.4(IN) ; also on sheet 7
VDDIO: C100.1 C212.1 C213.1 C214.1 C216.1 C217.1 C219.1 FL3.1 R216.2 R218.1 R219.1 R225.1 R226.1 R227.1 R228.1 R229.1 R230.2 R231.2 R232.2 R233.2 U16.5(QOD) U16.6(VOUT) U35.18(VDDIO) U35.30(VDDIO) ; also on sheet 7
CLK_OUT2: TP62.1(TP) U35.40(CLK_OUT)
ETH_EARTH: J7.15(SH1) J7.16(SH2)
GPIO_ICSSM1_RST: R217.1 U36.1(A) ; also on sheet 12
HSEC_EPWM21_A: R209.2 ; also on sheet 6
HSEC_EPWM21_B: R207.2 ; also on sheet 6
ICSSM1_ETH_LED2: J7.12 Q6.3(D)
ICSSM1_INTn: R214.2 U35.44(INT_N/PWDN_N) ; also on sheet 27
ICSSM1_LED_GREEN: J7.13 Q7.3(D) R218.2
ICSSM1_LED_YELLOW: J7.14 Q8.3(D) R219.2
ICSSM1_RESETn: R220.2 U35.43(RESET_N) U36.4(Y)
ICSSM_MII0/MII1_RXCLK_ON: R212.1 ; also on sheet 33
ICSSM_MII0/MII1_RXD0_ON: R225.2 R237.1 U35.33(RX_D0) ; also on sheet 33
ICSSM_MII0/MII1_RXD1_ON: R226.2 R238.1 U35.34(RX_D1) ; also on sheet 33
ICSSM_MII0/MII1_RXD2_ON: R231.1 R243.2 U35.35(RX_D2) ; also on sheet 33
ICSSM_MII0/MII1_RXD3_ON: R232.1 R244.2 U35.36(RX_D3) ; also on sheet 33
ICSSM_MII0/MII1_RXDV_ON: R230.1 R242.1 U35.38(RX_CTRL/RX_DV) ; also on sheet 33
ICSSM_MII0/MII1_RXER_ON: R213.2 R223.1 R228.2 R240.1 ; also on sheet 33
ICSSM_MII0/MII1_RXLINK_ON: R222.1 R227.2 R239.1 U35.47(LED_0) ; also on sheet 33
ICSSM_MII0/MII1_TXCLK_ON: R210.1 ; also on sheet 33
ICSSM_MII0/MII1_TXD0_ON: U35.28(TX_D0) ; also on sheet 33
ICSSM_MII0/MII1_TXD1_ON: U35.27(TX_D1) ; also on sheet 33
ICSSM_MII0/MII1_TXD2_ON: U35.26(TX_D2) ; also on sheet 33
ICSSM_MII0/MII1_TXD3_ON: U35.25(TX_D3) ; also on sheet 33
ICSSM_MII0/MII1_TXEN_ON: U35.37(TX_CTRL/TX_EN) ; also on sheet 33
JTAG_TDO2/GPIO_1: R233.1 R245.1 U35.22(JTAG_TDO/GPIO_1)
LED2_2: R221.1 R229.2 R241.1 U35.45(LED_2/GPIO_0)
MDIO0_MDC: U81.3(A1) ; also on sheet 7 12
MDIO0_MDIO: U81.7(B1) ; also on sheet 7 12
MDIO/MDC_MUX_SEL1: R474.1 U81.1(SEL) ; also on sheet 12
PORZ: U36.2(B) ; also on sheet 6 7 10 11 24 27
PR0_MDIO0_MDC: R211.2 R470.2 U81.2(A0) ; also on sheet 7
PR0_MDIO0_MDC_ON: R472.2 U35.42(MDC) U81.4(A)
PR0_MDIO0_MDIO: R208.2 R471.2 U81.8(B0) ; also on sheet 7
PR0_MDIO0_MDIO_ON: R473.2 U35.41(MDIO) U81.6(B)
PR0_PRU0_GPIO0: U1.K17(PR0_PRU0_GPIO0) ; also on sheet 32
PR0_PRU0_GPIO1: U1.K18(PR0_PRU0_GPIO1) ; also on sheet 32
PR0_PRU0_GPIO2: U1.J18(PR0_PRU0_GPIO2) ; also on sheet 32
PR0_PRU0_GPIO3: U1.J17(PR0_PRU0_GPIO3) ; also on sheet 32
PR0_PRU0_GPIO4: U1.K16(PR0_PRU0_GPIO4) ; also on sheet 32
PR0_PRU0_GPIO5: U1.G17(PR0_PRU0_GPIO5) ; also on sheet 32
PR0_PRU0_GPIO6: U1.K15(PR0_PRU0_GPIO6) ; also on sheet 32
PR0_PRU0_GPIO8: U1.G15(PR0_PRU0_GPIO8) ; also on sheet 32
PR0_PRU0_GPIO9: U1.F17(PR0_PRU0_GPIO9) ; also on sheet 32
PR0_PRU0_GPIO10: U1.G18(PR0_PRU0_GPIO10) ; also on sheet 32
PR0_PRU0_GPIO11: U1.M16(PR0_PRU0_GPIO11) ; also on sheet 32
PR0_PRU0_GPIO12: U1.M15(PR0_PRU0_GPIO12) ; also on sheet 32
PR0_PRU0_GPIO13: U1.H17(PR0_PRU0_GPIO13) ; also on sheet 32
PR0_PRU0_GPIO14: U1.H16(PR0_PRU0_GPIO14) ; also on sheet 32
PR0_PRU0_GPIO15: U1.L16(PR0_PRU0_GPIO15) ; also on sheet 32
PR0_PRU0_GPIO16: U1.H18(PR0_PRU0_GPIO16) ; also on sheet 32
PR0_PRU0_REF_CLK: U35.20(XI) ; also on sheet 9
R_LED2_0: J7.11 R216.1
RBIAS2: R215.1 TP63.1(TP) U35.12(RBIAS)
RJ45_ETH0_D0_N: J7.10(MX0-) U35.2(TD_M_A)
RJ45_ETH0_D0_P: J7.9(MX0+) U35.1(TD_P_A)
RJ45_ETH0_D1_N: J7.8(MX1-) U35.5(TD_M_B)
RJ45_ETH0_D1_P: J7.7(MX1+) U35.4(TD_P_B)
RJ45_ETH0_D2_N: J7.6(MX2-) U35.8(TD_M_C)
RJ45_ETH0_D2_P: J7.5(MX2+) U35.7(TD_P_C)
RJ45_ETH0_D3_N: J7.4(MX3-) U35.11(TD_M_D)
RJ45_ETH0_D3_P: J7.3(MX3+) U35.10(TD_P_D)
VMAIN: C93.1 U14.7(PVIN) U14.8(AVIN) ; also on sheet 1 4 10 26 27 29
VSYS_3V3_LDO1: C98.1 C189.1 C356.1 R78.2 R80.1 R214.1 R217.2 R470.1 R471.1 R472.1 R473.1 R474.2 U16.1(VIN) U36.5(VCC) U81.10(VCC) ; also on sheet 1 6 7 9 10 11 12 13 16 17 24 26 27 28 29 30 32 33
N32995593: R77.1 R79.1 U14.4(FB)
N32995608: L6.1 U14.2(SW)
N32995634: C95.1 U14.9(SS/TR)
N34778760: TP61.1(TP) U35.13(VDDA1P8_1) U35.48(VDDA1P8_2)
N34779936: Q7.1(G) R222.2
N34780102: R207.1 R211.1 U1.L18(PR0_MDIO0_MDC)
N34780104: R208.1 R209.1 U1.L17(PR0_MDIO0_MDIO)
N34780660: FL3.2 J7.2(VCC)
N34780919: Q8.1(G) R223.2
N34780978: R210.2 U35.29(GTX_CLK/TX_CLK)
N34780980: R213.1 U35.46(LED_1/RX_ER)
N34780998: R212.2 U35.32(RX_CLK)
N34781014: Q6.1(G) R221.2
N34781978: R81.2 U15.3(EN)
N34798910: C99.1 U16.4(CT)
N35824901: R475.2 U81.9(~{EN})

Not connected (* = marked no-connect by the designer): U14 10(MODE)*; U35 14(SON)* 15(SOP)* 16(SIP)* 17(SIN)* 19(XO)* 21(JTAG_CLK/TX_ER)* 23(JTAG_TMS)* 24(JTAG_TDI/SD)*

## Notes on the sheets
sheet 14
- Ethernet Powers
- 2.5V ETHERNET PHY POWER SUPPLY
- 1.1V, 0.5AMPS SUPPLY
- FOR INDUS PHY
- Load Switch
sheet 15
- RJ45
- PRU0 ICSS MII0, CPSW RGMII/MII Ethernet
- Phy ID: 0000
- RESET
- From IO Exp
- LED Driver MOSFETS
- Place Near power pins of 10/100/1000 Ethernet PHY
- MDIO/MDC MUX FOR ON-BOARD PHY
- Strapping Resistors
- PHY ADDRESS = 00000
  Auto-negotiation, 10/100/1000 advertised, Auto-MDI-X
  RGMII to Copper (1000BaseT/100Base-TX/10Base-Te)
